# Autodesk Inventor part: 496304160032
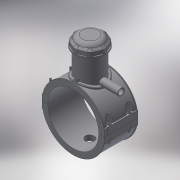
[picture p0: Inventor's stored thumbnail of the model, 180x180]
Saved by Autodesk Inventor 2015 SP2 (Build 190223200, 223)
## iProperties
Created: 2017-07
Part Number: 496304160032
Material: Generic
Description: PLASSON TAPPING SADDLE 160x32
Document SubType Name: Modeling
Designer: KIM
Mass: 1019.76 g
Surface Area: 2309.41 cm^2
Volume: 1019.76 cm^3
Density: 1 g/cm^3
Appearance: Default
Author: KIM
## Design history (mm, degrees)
derived "496304.ipt"
feature "Solid1::496304.ipt"
feature "Solid2::496304.ipt"
feature "Solid4::496304.ipt"
feature "Solid5::496304.ipt"
tag "TaggingFeature1"
body "Solid1"
body "Solid2"
other parameters: "d2" = 199, "d4" = 118, "d5" = 0, "d6" = 0.1, "d8" = 0, "d19" = 6, "d20" = 6, "d21" = 70.8, "d23" = 0, "d24" = 35.4, "d26" = 0, "d29" = 3, "d30" = 53.33333, "d31" = 6, "d32" = 0, "d33" = 0, "d34" = 0.6, "d40" = 94.848, "d41" = 72, "d43" = 0, "d45" = 0, "d47" = 162, "d70" = 15, "d72" = 0, "d73" = 6, "d75" = 5, "d76" = 0, "d77" = 8, "d79" = 15, "d80" = 47.2, "d82" = 5 deg, "d84" = 4, "d85" = 14, "d86" = 0, "d87" = 3, "d88" = 0, "d89" = 1, "d90" = 1, "d91" = 94.4, "d92" = 0, "d93" = 0.5, "d94" = 84.21053, "d96" = 186.048, "d97" = 2.36, "d98" = 0, "d102" = 1.6, "d120" = 140 deg, "d121" = 24.228, "d122" = 20 deg, "d123" = 364.8, "d124" = 109.44, "d126" = 0, "d143" = 164.8, "d145" = 17.23077, "d149" = 2.4, "d150" = 18.95385, "d153" = 118, "d154" = 0, "d156" = 91.2, "d157" = 160 deg, "d159" = 4.48, "d161" = 2.4, "d162" = 70.8, "d163" = 0, "d167" = 16, "d168" = 88.97561, "d170" = 3.375, "d172" = 0, "d173" = 1, "d176" = 20 deg, "d177" = 11.2, "d178" = 22.4, "d180" = 0, "d183" = 8.96, "d184" = 8.96, "d185" = 38.35, "d186" = 38.35, "d187" = 91.2, "d188" = 6.72, "d189" = 11.2, "d190" = 0, "d191" = 136.8, "d193" = 6.3, "d194" = 4.13, "d195" = 90 deg, "d197" = 0, "d199" = 0, "d200" = 11.2, "d202" = 0, "d203" = 138, "d204" = 68.4, "d205" = 50.4, "d206" = 61.2, "d207" = 103.5, "d208" = 107.64, "d209" = 128.34, "d210" = 61.92, "d211" = 72, "d212" = 57.6, "d213" = 0, "d216" = 0, "d217" = 16, "d218" = 16, "d219" = 3.2, "d224" = 0, "d230" = 3.2, "d233" = 6, "d236" = 99.5, "d237" = 35.4, "d238" = 6.02433, "d240" = 35.4, "d241" = 35.4, "d242" = 35.4, "d243" = 6, "d244" = 35.4, "d245" = 35.4, "d246" = 35.4, "d247" = 6, "d248" = 6, "d249" = 6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
